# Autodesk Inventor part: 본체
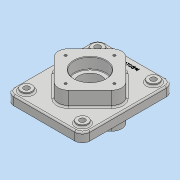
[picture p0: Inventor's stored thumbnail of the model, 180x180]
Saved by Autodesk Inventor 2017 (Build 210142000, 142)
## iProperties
Part Number: 본체
Material: 일반
Document SubType Name: Modeling
Designer: MRC
Density: 1 g/cm^3
Appearance: 기본값
Author: MRC
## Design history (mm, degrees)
sketch "스케치1"
  geometry: L1 (-75, -90)-(75, -90); L2 (75, -90)-(75, 90); L3 (75, 90)-(-75, 90); L4 (-75, 90)-(-75, -90); L5 (-75, -90)-(75, 90); L6 (75, -90)-(-75, 90); 1 further point
  constraints: 12 end point, 2 midpoint, 2 parallel, 1 horizontal, 1 perpendicular
  dimensions: "d0" = 150 distance of L2.end L3.end; "d1" = 180 distance of L3.end L1.start
extrude "돌출1" new body sketch "스케치1" distance "d2" = 18; taper "d3" = 0 deg
sketch "스케치2"
  geometry: L1 (0, -70.711)-(70.711, 0); L2 (70.711, 0)-(0, 70.711); L3 (0, 70.711)-(-70.711, 0); L4 (-70.711, 0)-(0, -70.711); L5 (0, -70.711)-(0, 70.711); L6 (70.711, 0)-(-70.711, 0); 1 further point
  constraints: 12 end point, 2 midpoint, 2 parallel, 1 horizontal, 1 perpendicular, 1 vertical
  dimensions: "d4" = 100 distance of L3.end L1.start
extrude "돌출2" join sketch "스케치2" distance "d5" = 29; taper "d6" = 0 deg
sketch "스케치3"
  geometry: L1 (0, -70.711)-(-70.711, 0) reference; L2 (-70.711, 0)-(0, 70.711) reference; L3 (0, 70.711)-(70.711, 0) reference; L4 (70.711, 0)-(0, -70.711) reference; 1 further point
extrude "돌출3" join sketch "스케치3" distance "d7" = 23; taper "d8" = 0 deg
fillet "모깎기1" dims "d9" = 15
sketch "스케치4"
  geometry: L1 (-75, 75)-(-75, -75) reference; L2 (-60, -90)-(60, -90) reference; L3 (75, -75)-(75, 75) reference; L4 (60, 90)-(-60, 90) reference; L5 (0, -70.711)-(-70.711, 0) reference; L6 (-70.711, 0)-(0, 70.711) reference; L7 (0, 70.711)-(70.711, 0) reference; L8 (70.711, 0)-(0, -70.711) reference; A1 r 15 centre (-60, 75) between (-60, 90) and (-75, 75) reference; A2 r 15 centre (-60, -75) between (-75, -75) and (-60, -90) reference; A3 r 15 centre (60, -75) between (60, -90) and (75, -75) reference; A4 r 15 centre (60, 75) between (75, 75) and (60, 90) reference; 3 further points
  constraints: 1 midpoint, 1 vertical alignment, 1 other
  dimensions: "d54" = 15 distance of point (0, 75) point (0, 90)
feature "엠보싱1" sketch "스케치4" dims "d0" = 150, "d1" = 180, "d11" = 0.5, "d12" = 0
fillet "모깎기2" dims "d13" = 20
sketch "스케치5"
  geometry: 1 further point
hole "구멍1" sketch "스케치5" at (0, 0) diameter "d14" = 45; stored, may be unused: countersink angle "d18" = 90 deg, drill point angle "d20" = 0 deg; dims "d15" = 6, "d16" = 62, "d17" = 22, "d19" = 100
sketch "스케치6"
  geometry: C1 r 31 at (0, 0); 1 further point
  constraints: 1 centre point, 1 coincident
  dimensions: "d21" = 62 diameter of C1
extrude "돌출4" cut sketch "스케치6" distance "d22" = 22; taper "d23" = 0 deg
sketch "스케치7"
  geometry: C1 r 11 at (-55, -70); 1 further point
  constraints: 1 centre point
  dimensions: "d24" = 22 diameter of C1; "d25" = 55 horizontal distance of point (0, 0) C1.centre; "d26" = 70 vertical distance of point (0, 0) C1.centre
extrude "돌출5" join sketch "스케치7" distance "d27" = 5; taper "d28" = 0 deg
sketch "스케치8"
  geometry: C1 r 5.5 at (0, 0); C2 r 11 at (0, 0) reference; 1 further point
  constraints: 1 centre point, 1 concentric
  dimensions: "d29" = 11 diameter of C1
extrude "돌출6" cut sketch "스케치8" stored distance "d30" = 5; taper "d31" = 0 deg
sketch "스케치9"
  geometry: 2 further points
  constraints: 1 vertical alignment
  dimensions: "d38" = 48 distance of point (0, 48) point (0, 0)
hole "구멍2" sketch "스케치9" at (0, 48) diameter "d39" = 4.917; stored, may be unused: countersink angle "d43" = 90 deg, drill point angle "d45" = 118 deg; dims "d40" = 10, "d41" = 62, "d42" = 22, "d44" = 13
node "작업 평면1"
fillet "모깎기3" dims "d49" = 3
fillet "모깎기4" dims "d50" = 1
chamfer "모따기1" distance "d51" = 1; stored, may be unused: second distance "d52" = 2, angle "d53" = 45 deg
node "솔리드1"
pattern_linear "직사각형 패턴1" dims "d34" = 110, "d37" = 140
pattern_circular "원형 패턴1" dims angle "d47" = 360 deg
mirror "미러1"
node "투영된 루프1"
node "투영된 루프2"
